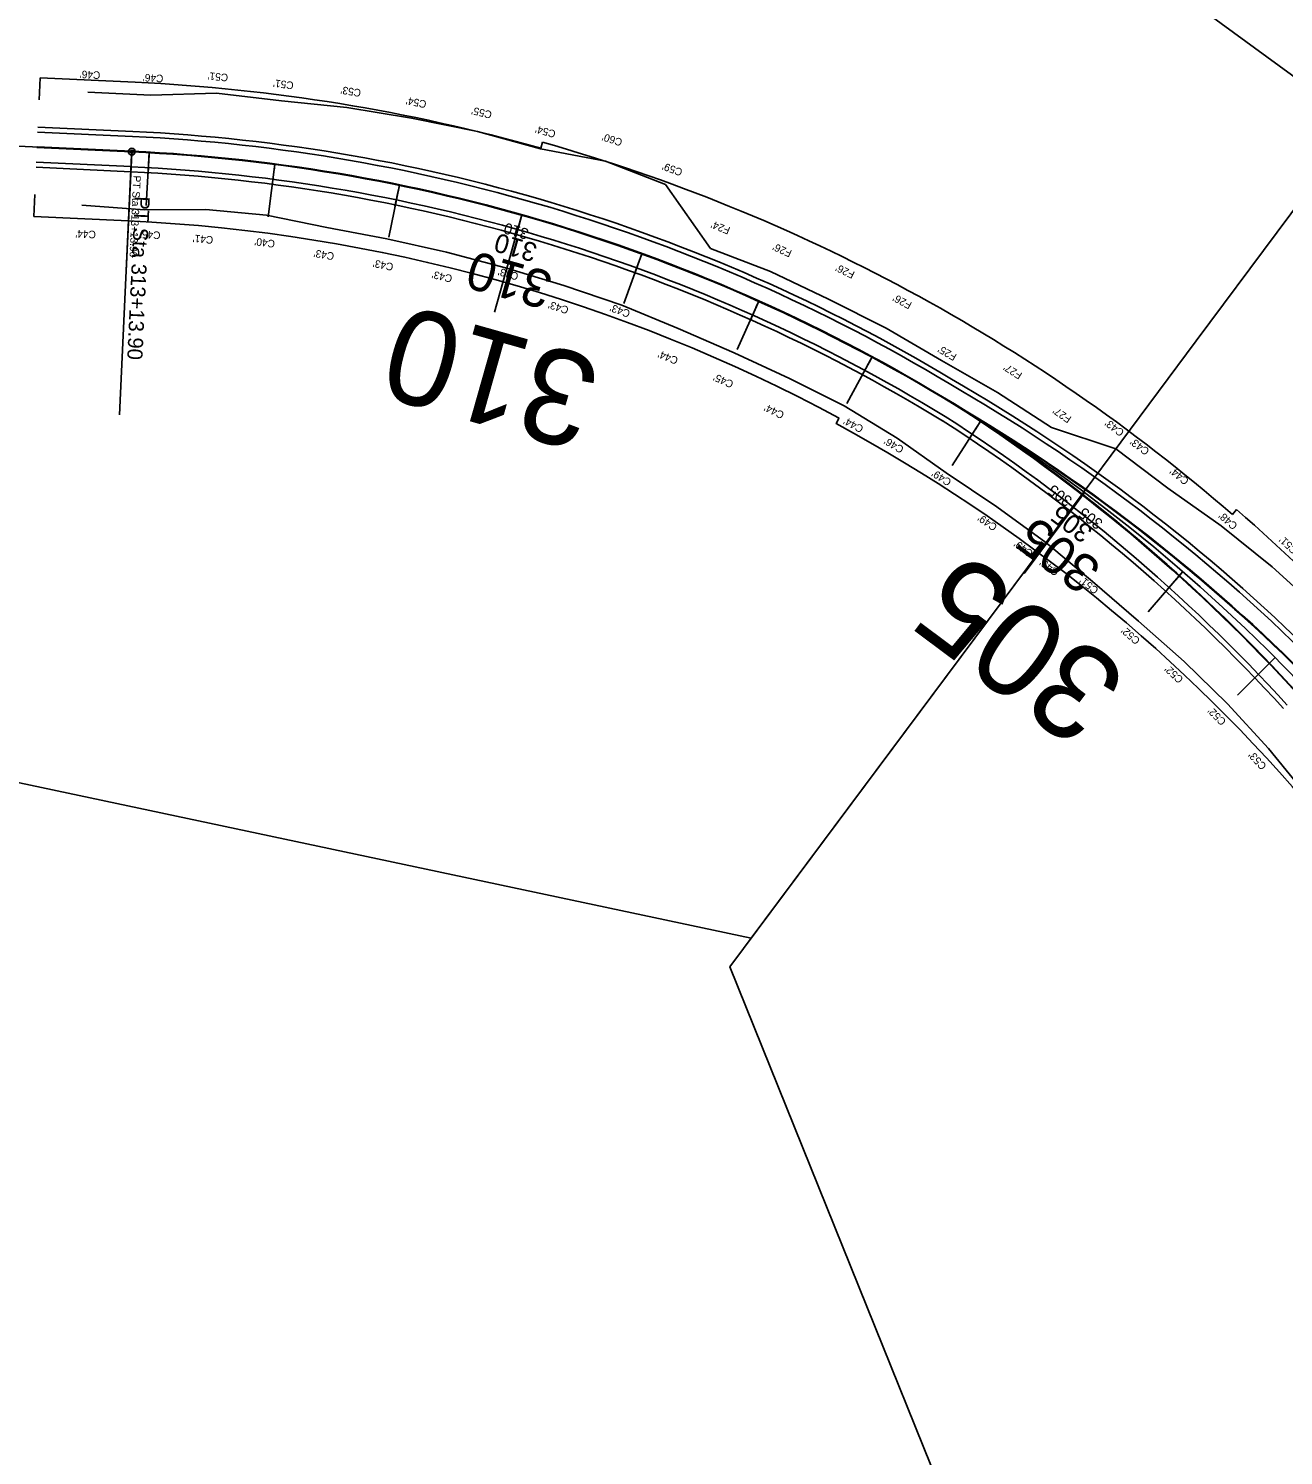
# Model space of a CAD drawing. Extents: x 2358865 to 2362945, y 393485 to 404880.
# Drawn here: x 2360591 to 2361585, y 401291 to 402421 of the extents above; entities that cross this region are included whole.
import ezdxf

# ---------------------------------------------------------------- set-up
doc = ezdxf.new("R2010")
doc.units = 0
for name, color, linetype in [('CL', 7, 'Continuous'), ('Level 11', 7, 'Continuous'), ('Level 19', 7, 'Continuous'), ('Level 25', 7, 'Continuous'), ('Level 27', 7, 'Continuous'), ('Level 28', 7, 'Continuous'), ('Level 30', 7, 'Continuous'), ('Level 33', 7, 'Continuous'), ('Level 37', 7, 'Continuous'), ('Level 39', 7, 'Continuous'), ('Level 41', 7, 'Continuous'), ('Level 48', 7, 'Continuous'), ('Level 50', 7, 'Continuous'), ('Level 51', 7, 'Continuous'), ('Level 52', 7, 'Continuous'), ('Level 53', 7, 'Continuous'), ('Level 63', 7, 'Continuous')]:
    doc.layers.add(name, color=color, linetype=linetype)

msp = doc.modelspace()

# ---------------------------------------------------------------- linework, layer by layer
at = {"layer": 'CL'}
msp.add_line((2360672.4, 402323.8), (2359068.7, 402398.7), dxfattribs=at)
msp.add_arc((2360608.6, 400955.3), 1370, 315.7519, 87.327, dxfattribs=at)
at = {"layer": 'Level 11'}
for p, q in [((2360673.2, 402339.8), (2360598, 402343.3)), ((2360671.7, 402307.9), (2360596.5, 402311.4))]:
    msp.add_line(p, q, dxfattribs=at)
for centre, radius, start, end in [((2360608.6, 400955.3), 1386, 58.5604, 87.327), ((2360608.6, 400955.3), 1354, 58.5604, 87.327), ((2360631.2, 400937.8), 1389.5, 44.6745, 59.7367), ((2360586.7, 400973.8), 1350, 42.3008, 57.3633)]:
    msp.add_arc(centre, radius, start, end, dxfattribs=at)
at = {"layer": 'Level 19'}
for p, q in [((2360673, 402335.8), (2360597.8, 402339.3)), ((2360671.9, 402311.9), (2360596.7, 402315.4))]:
    msp.add_line(p, q, dxfattribs=at)
for centre, radius, start, end in [((2360608.6, 400955.3), 1382, 58.5604, 87.327), ((2360608.6, 400955.3), 1358, 58.5604, 87.327), ((2360631.2, 400937.8), 1385.5, 44.6745, 59.7367), ((2360586.7, 400973.8), 1354, 42.3008, 57.3633)]:
    msp.add_arc(centre, radius, start, end, dxfattribs=at)
at = {"layer": 'Level 25'}
for p, q in [((2360686.3, 402323.1), (2360686, 402318.1)), ((2360785.9, 402313.8), (2360785.2, 402308.9)), ((2360884.5, 402297.3), (2360883.5, 402292.4)), ((2360981.6, 402273.6), (2360979.4, 402265.9)), ((2361076.7, 402242.9), (2361075, 402238.2)), ((2361169.4, 402205.3), (2361167.3, 402200.7)), ((2361259.1, 402161.1), (2361256.7, 402156.7)), ((2361345.2, 402110.4), (2361342.6, 402106.2)), ((2361427.5, 402053.6), (2361422.7, 402047.2)), ((2361505.4, 401991), (2361502.2, 401987.2)), ((2361578.6, 401922.8), (2361575, 401919.3))]:
    msp.add_line(p, q, dxfattribs=at)
at = {"layer": 'Level 27'}
for p, q in [((2360599.8, 402382.3), (2360599, 402364.8)), ((2360675, 402378.8), (2360599.8, 402382.3)), ((2360997.9, 402331.3), (2360996.6, 402326.5)), ((2360595.5, 402289.9), (2360594.7, 402272.4)), ((2360669.9, 402268.9), (2360594.7, 402272.4)), ((2361230.6, 402108.2), (2361232.9, 402112.6)), ((2361548, 402040.1), (2361544.7, 402036.3))]:
    msp.add_line(p, q, dxfattribs=at)
for radius, start, end in [(1425, 74.1992, 87.327), (1430, 49.1062, 74.1992), (1315, 61.6527, 87.327), (1310, 18.3189, 61.6527), (1435, 25.2435, 49.1062)]:
    msp.add_arc((2360608.6, 400955.3), radius, start, end, dxfattribs=at)
at = {"layer": 'Level 28'}
msp.add_line((2360672.4, 402322.6), (2360667.5, 402218.3), dxfattribs=at)
msp.add_circle((2360672.4, 402323.8), 1.25, dxfattribs=at)
at = {"layer": 'Level 30'}
for p, q in [((2360686.3, 402323.1), (2360685.8, 402314.6)), ((2360785.9, 402313.8), (2360784.8, 402305.4)), ((2360884.5, 402297.3), (2360882.8, 402288.9)), ((2360981.6, 402273.6), (2360977.2, 402258.2)), ((2361076.7, 402242.9), (2361073.8, 402234.9)), ((2361169.4, 402205.3), (2361165.9, 402197.5)), ((2361259.1, 402161.1), (2361255, 402153.6)), ((2361345.2, 402110.4), (2361340.7, 402103.2)), ((2361427.5, 402053.6), (2361418, 402040.8)), ((2361505.4, 401991), (2361499.9, 401984.5)), ((2361578.6, 401922.8), (2361572.6, 401916.8))]:
    msp.add_line(p, q, dxfattribs=at)
at = {"layer": 'Level 33'}
msp.add_line((2360672.3, 402321.1), (2360662.7, 402115.1), dxfattribs=at)
msp.add_circle((2360672.4, 402323.8), 2.7, dxfattribs=at)
at = {"layer": 'Level 37'}
for p, q in [((2360672.4, 402323.6), (2360597.2, 402327.1)), ((2360672.5, 402324.1), (2360597.3, 402327.6))]:
    msp.add_line(p, q, dxfattribs=at)
for centre, radius, start, end in [((2360608.6, 400955.3), 1369.8, 58.0507, 87.327), ((2360608.6, 400955.3), 1370.3, 58.0508, 87.327), ((2360586.7, 400973.8), 1366, 42.3008, 56.8625), ((2360631.2, 400937.8), 1373.5, 44.6745, 59.2385), ((2360586.7, 400973.8), 1366.5, 42.3008, 56.3574), ((2360631.2, 400937.8), 1373, 44.6745, 58.7357)]:
    msp.add_arc(centre, radius, start, end, dxfattribs=at)
at = {"layer": 'Level 39'}
for p, q in [((2360686.3, 402323.1), (2360685.4, 402306.2)), ((2360785.9, 402313.8), (2360783.7, 402297)), ((2360884.5, 402297.3), (2360881, 402280.6)), ((2360981.6, 402273.6), (2360972.9, 402242.8)), ((2361076.7, 402242.9), (2361070.9, 402226.9)), ((2361169.4, 402205.3), (2361162.4, 402189.8)), ((2361259.1, 402161.1), (2361251, 402146.1)), ((2361345.2, 402110.4), (2361336.1, 402096.1)), ((2361427.5, 402053.6), (2361408.4, 402027.9)), ((2361505.4, 401991), (2361494.3, 401978.1)), ((2361578.6, 401922.8), (2361566.5, 401910.8))]:
    msp.add_line(p, q, dxfattribs=at)
at = {"layer": 'Level 41'}
for p, q in [((2360686.3, 402323.1), (2360683.9, 402281.2)), ((2360785.9, 402313.8), (2360780.4, 402272.2)), ((2360884.5, 402297.3), (2360876, 402256.1)), ((2360981.6, 402273.6), (2360959.8, 402196.6)), ((2361076.7, 402242.9), (2361062.4, 402203.4)), ((2361169.4, 402205.3), (2361152.2, 402167)), ((2361259.1, 402161.1), (2361239.1, 402124.1)), ((2361345.2, 402110.4), (2361322.7, 402075)), ((2361427.5, 402053.6), (2361379.7, 401989.5)), ((2361505.4, 401991), (2361477.9, 401959.2)), ((2361578.6, 401922.8), (2361548.8, 401893.1))]:
    msp.add_line(p, q, dxfattribs=at)
at = {"layer": 'Level 48'}
for centre, radius, start, end in [((2360631.2, 400937.8), 1373, 44.6799, 58.7357), ((2360586.7, 400973.8), 1366.5, 42.3191, 56.3574)]:
    msp.add_arc(centre, radius, start, end, dxfattribs=at)
at = {"layer": 'Level 50'}
for p, q in [((2360687.6, 402368.5), (2360637.5, 402371)), ((2360739.6, 402370.1), (2360687.6, 402368.5)), ((2360791.1, 402364.1), (2360739.6, 402370.1)), ((2360842.8, 402358.8), (2360791.1, 402364.1)), ((2360894.1, 402350.2), (2360842.8, 402358.8)), ((2360946.3, 402339.7), (2360894.1, 402350.2)), ((2360996.4, 402325.9), (2360946.3, 402339.7)), ((2361047.9, 402316.2), (2360996.4, 402325.9)), ((2361095.5, 402297.8), (2361047.9, 402316.2)), ((2360682.5, 402277.6), (2360632.8, 402281.3)), ((2360731, 402277.8), (2360682.5, 402277.6)), ((2360779.3, 402273.4), (2360731, 402277.8)), ((2360826.9, 402263.7), (2360779.3, 402273.4)), ((2360874.5, 402254.6), (2360826.9, 402263.7)), ((2360921.8, 402244.1), (2360874.5, 402254.6)), ((2360968.5, 402231.6), (2360921.8, 402244.1)), ((2361014.9, 402217.7), (2360968.5, 402231.6)), ((2361060.8, 402202.1), (2361014.9, 402217.7)), ((2361105.5, 402183.5), (2361060.8, 402202.1)), ((2361149.9, 402164.4), (2361105.5, 402183.5)), ((2361193.8, 402144.1), (2361149.9, 402164.4)), ((2361237.1, 402122.4), (2361193.8, 402144.1)), ((2361279.1, 402096.6), (2361237.1, 402122.4)), ((2361317.9, 402069.2), (2361279.1, 402096.6)), ((2361493.4, 402057.2), (2361452.3, 402088.3)), ((2361358, 402042.4), (2361317.9, 402069.2)), ((2361535.8, 402027.3), (2361493.4, 402057.2)), ((2361396.9, 402014), (2361358, 402042.4)), ((2361576.3, 401994.8), (2361535.8, 402027.3)), ((2361433.9, 401983.1), (2361396.9, 402014)), ((2361614.5, 401959.8), (2361576.3, 401994.8)), ((2361470.3, 401951.6), (2361433.9, 401983.1)), ((2361506.4, 401919.8), (2361470.3, 401951.6)), ((2361540.8, 401886.2), (2361506.4, 401919.8)), ((2361573.3, 401850.7), (2361540.8, 401886.2)), ((2361603.7, 401813.4), (2361573.3, 401850.7))]:
    msp.add_line(p, q, dxfattribs=at)
at = {"layer": 'Level 51'}
for p, q in [((2361178.7, 402228.7), (2361131.1, 402246.9)), ((2361224.7, 402206.8), (2361178.7, 402228.7)), ((2361270.2, 402183.8), (2361224.7, 402206.8)), ((2361314.2, 402158.2), (2361270.2, 402183.8)), ((2361358.5, 402133), (2361314.2, 402158.2)), ((2361401.2, 402105.1), (2361358.5, 402133))]:
    msp.add_line(p, q, dxfattribs=at)
at = {"layer": 'Level 52'}
for p, q in [((2361131.1, 402246.9), (2361095.5, 402297.8)), ((2361452.3, 402088.3), (2361401.2, 402105.1))]:
    msp.add_line(p, q, dxfattribs=at)
at = {"layer": 'Level 63'}
for points in [[(2359964.7, 401954.9), (2361163.4, 401700.4), (2361426.4, 402053.5), (2361426.4, 402053.5), (2361515.9, 402173.8), (2361644.3, 402346.2), (2361509.4, 402444.8), (2360042.1, 402756.3), (2359995.2, 402535.3), (2359995.2, 402535.3)], [(2361426.4, 402053.5), (2361146.5, 401677.8), (2361146.5, 401677.8), (2361497.4, 400807.4), (2361959.6, 400730.7), (2361959.6, 400730.7), (2362107.5, 400706.2), (2362344.7, 400666.9), (2362325.2, 400877.2), (2362269.7, 401052), (2361764.4, 402249.8), (2361644.3, 402346.2), (2361515.9, 402173.8)]]:
    msp.add_lwpolyline(points, close=True, dxfattribs=at)

# ---------------------------------------------------------------- texts
at = {"layer": 'Level 25'}
for s, rotation, p in [('310', 164.1992, (2360987.6, 402262.3)), ('305', 143.2884, (2361418.5, 402048.8)), ('305', 143.2884, (2361442.8, 402030.7))]:
    msp.add_text(s, height=8.75, rotation=rotation, dxfattribs=at).set_placement(p)
at = {"layer": 'Level 28'}
msp.add_text('PT Sta 313+13.90', height=6, rotation=267.327, dxfattribs=at).set_placement((2360673.6, 402305))
at = {"layer": 'Level 30'}
for s, rotation, p in [('310', 164.1992, (2360994.7, 402250.4)), ('305', 143.2884, (2361435, 402024.7))]:
    msp.add_text(s, height=15, rotation=rotation, dxfattribs=at).set_placement(p)
at = {"layer": 'Level 33'}
msp.add_text('PT Sta 313+13.90', height=12, rotation=267.327, dxfattribs=at).set_placement((2360674.8, 402288.7))
at = {"layer": 'Level 39'}
for s, rotation, p in [('310', 164.1992, (2361007.8, 402227.3)), ('305', 143.2884, (2361442.4, 401995.8))]:
    msp.add_text(s, height=30, rotation=rotation, dxfattribs=at).set_placement(p)
at = {"layer": 'Level 41'}
for s, rotation, p in [('310', 164.1992, (2361047.3, 402157.8)), ('305', 143.2884, (2361465.1, 401909))]:
    msp.add_text(s, height=75, rotation=rotation, dxfattribs=at).set_placement(p)
at = {"layer": 'Level 53'}
for s, rotation, p in [("C46'", 177.327, (2360647.6, 402387.3)), ("C46'", 176.8, (2360697.6, 402384.6)), ("C51'", 174.708, (2360749, 402385.3)), ("C51'", 172.6159, (2360801, 402379)), ("C53'", 170.5239, (2360854.5, 402373)), ("C54'", 168.4318, (2360906.4, 402364)), ("C55'", 166.3397, (2360958.3, 402355.6)), ("C54'", 164.2476, (2361008.9, 402340.3)), ("C60'", 162.1554, (2361061.8, 402333.6)), ("C59'", 160.0633, (2361109.5, 402309.8)), ("C44'", 177.327, (2360644.1, 402261)), ("C45'", 176.8, (2360695.3, 402260.4)), ("C41'", 174.708, (2360737.2, 402256.6)), ("F24'", 157.9711, (2361147.2, 402263.5)), ("C40'", 172.6159, (2360786.2, 402253.5)), ("C43'", 170.5239, (2360833.2, 402243.6)), ("F26'", 155.8789, (2361196.1, 402245.3)), ("C43'", 168.4318, (2360880.2, 402235.1)), ("C43'", 166.3397, (2360926.9, 402225.7)), ("C43'", 164.2476, (2360979.4, 402227.4)), ("F26'", 153.7867, (2361245.9, 402228.2)), ("C43'", 162.1554, (2361019.2, 402200.6)), ("C43'", 160.0633, (2361068, 402197.7)), ("F26'", 151.6944, (2361291.2, 402203.9)), ("F25'", 149.6022, (2361326.8, 402162.8)), ("C44'", 157.9711, (2361106, 402160.4)), ("C45'", 155.8789, (2361149.9, 402141.6)), ("F27'", 147.5099, (2361378.7, 402148)), ("C44'", 153.7867, (2361190.1, 402117)), ("C44'", 151.6944, (2361252.9, 402105.9)), ("F27'", 145.4177, (2361417.7, 402113.2)), ("C43'", 143.3254, (2361459.5, 402102.4)), ("C46'", 149.6022, (2361284.9, 402089.5)), ("C43'", 143.3254, (2361479.5, 402087.5)), ("C49'", 147.5099, (2361322.6, 402063.4)), ("C44'", 141.2331, (2361510.8, 402063.8)), ("C49'", 145.4177, (2361358.9, 402027.6)), ("C48'", 139.1409, (2361549.3, 402028.1)), ("C49'", 143.3254, (2361387.4, 402006.6)), ("C51'", 137.0486, (2361597, 402008.6)), ("C49'", 143.3254, (2361407.8, 401991.8)), ("C51'", 141.2331, (2361439.2, 401977.2)), ("C52'", 139.1409, (2361472.1, 401937.1)), ("C52'", 137.0486, (2361506.3, 401906.2)), ("C52'", 134.9563, (2361540.2, 401872.6)), ("C53'", 132.864, (2361572.2, 401837.2))]:
    msp.add_text(s, height=6, rotation=rotation, dxfattribs=at).set_placement(p)

doc.saveas('drawing.dxf')
